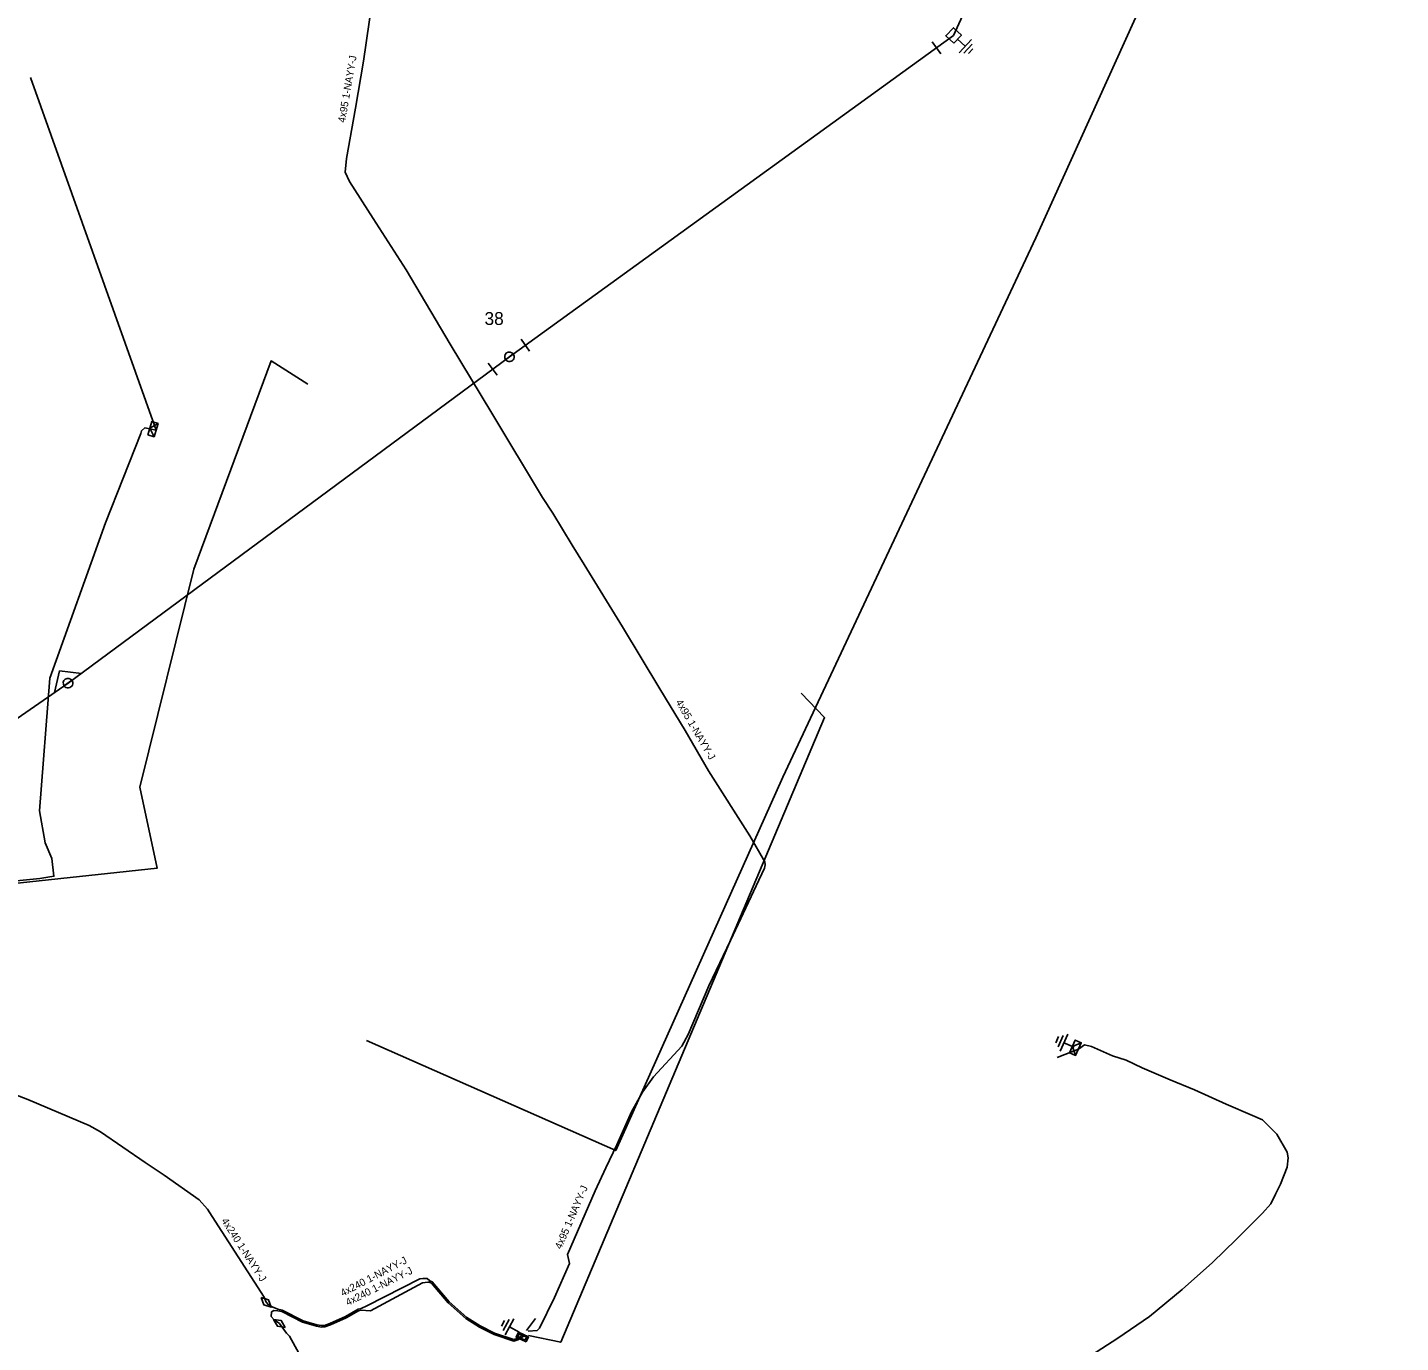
# Model space of a CAD drawing. Extents: x -540028 to -538776, y -1157064 to -1155670.
# Drawn here: x -539627.5 to -539441, y -1156879 to -1156700.4 of the extents above; entities that cross this region are included whole.
import ezdxf

# ---------------------------------------------------------------- set-up
doc = ezdxf.new("R2010")
doc.units = 0
for name, color, linetype in [('Implicitní', 7, 'Continuous'), ('Vrstva 13', 7, 'Continuous'), ('Vrstva 14', 7, 'Continuous'), ('Vrstva 15', 7, 'Continuous'), ('Vrstva 18', 7, 'Continuous'), ('Vrstva 19', 7, 'Continuous'), ('Vrstva 2', 7, 'Continuous'), ('Vrstva 28', 7, 'Continuous'), ('Vrstva 31', 7, 'Continuous'), ('Vrstva 5', 7, 'Continuous'), ('Vrstva 52', 7, 'Continuous'), ('Vrstva 59', 7, 'Continuous'), ('Vrstva 6', 7, 'Continuous')]:
    doc.layers.add(name, color=color, linetype=linetype)

# ---------------------------------------------------------------- blocks, each defined once
blk = doc.blocks.new('326')
at = {"layer": 'Vrstva 2'}
blk.add_line((0, 2), (0, -2), dxfattribs=at)
blk = doc.blocks.new('16')
at = {"layer": 'Vrstva 2'}
for p, q in [((-4.5, 0), (0, 4)), ((0, 4), (4.5, 0))]:
    blk.add_line(p, q, dxfattribs=at)
blk = doc.blocks.new('5')
at = {"layer": 'Implicitní'}
blk.add_line((1.3, 0), (-1.3, 0), dxfattribs=at)
blk.add_arc((0, 0), 1.3, 180, 0, dxfattribs=at)
at = {"layer": 'Vrstva 2'}
blk.add_arc((0, 0), 1.3, 0, 180, dxfattribs=at)
blk = doc.blocks.new('11')
at = {"layer": 'Vrstva 2'}
for p, q in [((0, -4.3), (0, -1.3)), ((-2.5, -4.3), (2.5, -4.3)), ((-1.7, -5.3), (1.7, -5.3)), ((-0.9, -6.3), (0.9, -6.3))]:
    blk.add_line(p, q, dxfattribs=at)
blk = doc.blocks.new('8')
at = {"layer": 'Vrstva 2'}
blk.add_lwpolyline([(-1.5, -1.5), (1.5, -1.5), (1.5, 1.5), (-1.5, 1.5)], close=True, dxfattribs=at)
blk = doc.blocks.new('17')
at = {"layer": 'Vrstva 2'}
blk.add_lwpolyline([(-1.875, 0), (0, 0.9375), (1.875, 0), (0, -0.9375)], close=True, dxfattribs=at)
blk = doc.blocks.new('132')
at = {"layer": 'Vrstva 2'}
for points in [[(-1.5, 1.5), (1.5, 1.5), (1.5, 0), (-1.5, 0)], [(-1.1, 1.2), (1.1, 1.2), (1.1, 0.3), (-1.1, 0.3)]]:
    blk.add_lwpolyline(points, close=True, dxfattribs=at)
blk = doc.blocks.new('23')
at = {"layer": 'Vrstva 2'}
blk.add_lwpolyline([(1.875, -1.8), (-1.875, -1.8), (-1.875, 0), (1.875, 0)], close=True, dxfattribs=at)
blk.add_lwpolyline([(1.875, 0), (0, -1.8), (-1.875, 0)], dxfattribs=at)

msp = doc.modelspace()

# ---------------------------------------------------------------- linework, layer by layer
at = {"layer": 'Vrstva 5'}
for points in [[(-539559.5, -1156877.44), (-539559.47, -1156877.43), (-539558.25, -1156877.36), (-539557.96, -1156877.06), (-539555.9, -1156872.87), (-539553.86, -1156868.24), (-539554.13, -1156867.04), (-539550.4, -1156858.39), (-539548.92, -1156855.28), (-539547.44, -1156852.15), (-539545.47, -1156847.67), (-539543.98, -1156844.98), (-539542.49, -1156842.92), (-539538.63, -1156838.75), (-539537.75, -1156837.18), (-539534.94, -1156830.54), (-539532.02, -1156824.38), (-539528.51, -1156816.99), (-539527.42, -1156814.56), (-539527.29, -1156814.14), (-539527.34, -1156813.73), (-539529.41, -1156810.2), (-539534.98, -1156801.35), (-539538.18, -1156795.87), (-539541.61, -1156790.21), (-539546.68, -1156781.81), (-539551.87, -1156773.35), (-539553.49, -1156770.71), (-539556.15, -1156766.36), (-539557.53, -1156764.25), (-539564.43, -1156752.79), (-539570.06, -1156743.42), (-539576.05, -1156733.31), (-539580.53, -1156726.34), (-539583.76, -1156721.34), (-539584.33, -1156720.06), (-539584.17, -1156718.2), (-539582.95, -1156711.38), (-539581.84, -1156705.01), (-539580.66, -1156696.9)], [(-539646, -1156825.68), (-539646.73, -1156826.66), (-539647.68, -1156828.36), (-539647.99, -1156830.13), (-539648.62, -1156832.05), (-539650.08, -1156836.63), (-539648.29, -1156837.47), (-539636.58, -1156842.32), (-539630.15, -1156844.96), (-539627.41, -1156846.01), (-539619.09, -1156849.52), (-539617.54, -1156850.38), (-539611.5, -1156854.55), (-539608.89, -1156856.26), (-539604.14, -1156859.61), (-539603.03, -1156860.9), (-539602.4, -1156861.86), (-539595.34, -1156872.82), (-539595.06, -1156873.53)], [(-539483.76, -1156881.21), (-539479.44, -1156878.38), (-539475.12, -1156875.46), (-539470.69, -1156871.79), (-539466.55, -1156868.12), (-539463.35, -1156864.99), (-539459.79, -1156861.41), (-539458.67, -1156860.16), (-539458.01, -1156858.84), (-539457.35, -1156857.5), (-539456.42, -1156855.16), (-539456.29, -1156853.93), (-539456.44, -1156853.14), (-539457.84, -1156850.7), (-539459.8, -1156848.77), (-539461.15, -1156848.15), (-539464.72, -1156846.62), (-539469, -1156844.7), (-539472.32, -1156843.31), (-539476.11, -1156841.71), (-539478.28, -1156840.66), (-539480.15, -1156840.08), (-539483.02, -1156838.78), (-539483.93, -1156838.57), (-539484.77, -1156839.15)], [(-539595.06, -1156873.53), (-539594.73, -1156873.86), (-539594.26, -1156874.14), (-539593.47, -1156874.47), (-539592.87, -1156874.6), (-539590.04, -1156876.03), (-539588.16, -1156876.59), (-539587.55, -1156876.69), (-539587.12, -1156876.67), (-539586.4, -1156876.39), (-539584.3, -1156875.44), (-539582.59, -1156874.48), (-539582.17, -1156874.38), (-539581.4, -1156873.99), (-539574.2, -1156870.35), (-539573.78, -1156870.28), (-539573.21, -1156870.31), (-539572.84, -1156870.61), (-539572.51, -1156870.76), (-539570.22, -1156873.45), (-539567.82, -1156875.58), (-539566.01, -1156876.73), (-539564.04, -1156877.73), (-539561.41, -1156878.59), (-539560.97, -1156878.47), (-539560.44, -1156878.15), (-539560.27, -1156877.82)], [(-539560.09, -1156877.92), (-539560.29, -1156878.29), (-539560.89, -1156878.65), (-539561.42, -1156878.8), (-539564.12, -1156877.91), (-539566.11, -1156876.91), (-539567.94, -1156875.74), (-539570.37, -1156873.59), (-539572.63, -1156870.92), (-539572.91, -1156870.8), (-539573.1, -1156870.78), (-539573.83, -1156870.9), (-539580.89, -1156874.67), (-539582.21, -1156874.6), (-539582.52, -1156874.67), (-539584.21, -1156875.62), (-539586.32, -1156876.57), (-539587.08, -1156876.87), (-539587.56, -1156876.89), (-539588.21, -1156876.79), (-539590.11, -1156876.21), (-539592.94, -1156874.79), (-539593.48, -1156874.67), (-539594.06, -1156874.64), (-539594.35, -1156874.86), (-539594.39, -1156875.45), (-539593.98, -1156875.91), (-539593.27, -1156876.4)], [(-539593.27, -1156876.4), (-539592.29, -1156877.71), (-539591.91, -1156878.14), (-539589.65, -1156882.26), (-539581.78, -1156898.74), (-539581.33, -1156899.22), (-539580.52, -1156899.63), (-539577.27, -1156902.13), (-539573.34, -1156904.99), (-539571.9, -1156906.11), (-539571.14, -1156906.85), (-539569.76, -1156909.02), (-539569.31, -1156909.35), (-539540.12, -1156911.88), (-539538.41, -1156911.85), (-539536.83, -1156911.74), (-539532.56, -1156911.23), (-539530.86, -1156911.33), (-539529.53, -1156911.92), (-539528.55, -1156912.83), (-539524.85, -1156920.51), (-539523.76, -1156921.84), (-539522.77, -1156922.53), (-539512.75, -1156929.47)]]:
    msp.add_lwpolyline(points, dxfattribs=at)
at = {"layer": 'Vrstva 52'}
for points in [[(-539657.4, -1156814), (-539621.96, -1156789.44), (-539562.03, -1156745.14), (-539501.72, -1156701.5), (-539461.47, -1156613.51), (-539433.27, -1156551.44), (-539397.51, -1156471.99), (-539336.12, -1156442.56)], [(-539644.6, -1156812.23), (-539643.59, -1156812.39), (-539637.15, -1156817.13), (-539625.77, -1156815.98), (-539623.87, -1156815.67), (-539624.18, -1156813.28), (-539625.07, -1156811.15), (-539625.85, -1156806.79), (-539624.44, -1156788.79), (-539616.86, -1156767.7), (-539612.09, -1156755.55), (-539611.99, -1156755.19), (-539611.53, -1156754.8), (-539610.01, -1156755.09)]]:
    msp.add_lwpolyline(points, dxfattribs=at)
at = {"layer": 'Vrstva 59'}
for points in [[(-539476.45, -1156646.5), (-539478.22, -1156665.48), (-539468.73, -1156680.79), (-539490.57, -1156728.99), (-539524.92, -1156802.24), (-539547.6, -1156852.94), (-539581.45, -1156837.99)], [(-539610.01, -1156755.09), (-539627.06, -1156707.19)], [(-539644.11, -1156824.72), (-539636.49, -1156817.42), (-539609.87, -1156814.59), (-539612.2, -1156803.6), (-539604.88, -1156773.99), (-539594.4, -1156745.7), (-539589.41, -1156748.86)], [(-539559.45, -1156878.04), (-539555.06, -1156878.95), (-539519.24, -1156794.13), (-539522.44, -1156790.79)], [(-539484.77, -1156839.15), (-539487.67, -1156840.3)], [(-539559.7, -1156877.34), (-539558.47, -1156875.75)]]:
    msp.add_lwpolyline(points, dxfattribs=at)

# ---------------------------------------------------------------- block references
at = {"layer": 'Vrstva 13', "xscale": 0.5}
for name, p, yscale, rotation in [('8', (-539501.72, -1156701.5), 0.5000000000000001, 46.957275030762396), ('5', (-539562.03, -1156745.14), 0.5, 36.47189445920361), ('5', (-539621.96, -1156789.44), 0.5, 34.72251112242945)]:
    msp.add_blockref(name, p, dxfattribs=dict(at, yscale=yscale, rotation=rotation))
at = {"layer": 'Vrstva 15', "xscale": 0.5, "yscale": 0.5}
for p, rotation in [((-539501.72, -1156701.5), 47.28581944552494), ((-539484.77, -1156839.15), -114.02455230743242), ((-539560.13, -1156877.9), -118.51554364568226)]:
    msp.add_blockref('11', p, dxfattribs=dict(at, rotation=rotation))
at = {"layer": 'Vrstva 18', "yscale": 0.5}
for name, p, xscale, rotation in [('326', (-539504.04, -1156703.18), 0.5, 35.88930277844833), ('326', (-539559.87, -1156743.57), 0.5, -144.1106972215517), ('326', (-539564.31, -1156746.82), 0.49999999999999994, 36.47165276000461), ('16', (-539621.96, -1156789.44), 0.5, 34.72243605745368)]:
    msp.add_blockref(name, p, dxfattribs=dict(at, xscale=xscale, rotation=rotation))
at = {"layer": 'Vrstva 19'}
for p, xscale, yscale, rotation in [((-539595.06, -1156873.53), 0.5, 0.5, -45.00000009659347), ((-539593.27, -1156876.4), 0.49999999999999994, 0.5000000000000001, 145.38885787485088)]:
    msp.add_blockref('17', p, dxfattribs=dict(at, xscale=xscale, yscale=yscale, rotation=rotation))
at = {"layer": 'Vrstva 28', "xscale": 0.49999999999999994, "yscale": 0.5, "rotation": 154.49034282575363}
msp.add_blockref('132', (-539560.13, -1156877.9), dxfattribs=at)
at = {"layer": 'Vrstva 31', "xscale": 0.5, "yscale": 0.5000000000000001}
for p, rotation in [((-539610.01, -1156755.09), -107.31202501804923), ((-539484.77, -1156839.15), -113.99092257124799)]:
    msp.add_blockref('23', p, dxfattribs=dict(at, rotation=rotation))

# ---------------------------------------------------------------- texts
at = {"layer": 'Vrstva 14'}
msp.add_text('38', height=1.75, dxfattribs=at).set_placement((-539565.41, -1156740.81))
at = {"layer": 'Vrstva 6'}
for s, rotation, p in [('4x95 1-NAYY-J', 80.115, (-539584.35, -1156713.39)), ('4x95 1-NAYY-J', 300.282, (-539539.5, -1156792.01)), ('4x95 1-NAYY-J', 66.674, (-539555, -1156866.4)), ('4x240 1-NAYY-J', 302.796, (-539601.19, -1156862.47)), ('4x240 1-NAYY-J', 27.61, (-539584.66, -1156872.77)), ('4x240 1-NAYY-J', 26.819, (-539583.96, -1156874.05))]:
    msp.add_text(s, height=1, rotation=rotation, dxfattribs=at).set_placement(p)

doc.saveas('drawing.dxf')
